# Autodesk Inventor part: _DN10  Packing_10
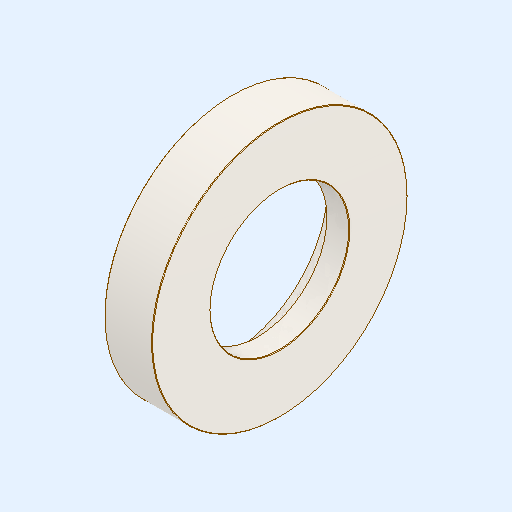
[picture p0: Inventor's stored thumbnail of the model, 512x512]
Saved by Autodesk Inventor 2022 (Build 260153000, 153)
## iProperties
Created: 2021-12
Part Number: _DN10  Packing_10
Material: Generico
Document SubType Name: Modeling
Designer: admin
Density: 1 g/cm^3
Appearance: Default
Author: admin
Revision Number: NONE
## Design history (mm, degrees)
feature "_DN10  Packing"
node "Solido1"
